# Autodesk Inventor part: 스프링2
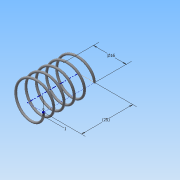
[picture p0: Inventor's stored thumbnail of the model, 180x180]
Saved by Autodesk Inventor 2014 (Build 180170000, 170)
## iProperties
Created: 2015-06
Part Number: 스프링2
Material: 강철, 연강
Document SubType Name: Modeling
Designer: Administrator
Density: 7.86 g/cm^3
Appearance: 강철
Mass: 1.52988 g
Surface Area: 7.87024 cm^2
Volume: 0.194641 cm^3
Author: Administrator
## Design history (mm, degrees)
sketch "스케치1"
  geometry: L1 (0, 0)-(8, 0); L2 (8, 0)-(8, 14.5); L3 (8, 14.5)-(0, 14.5); L4 (0, 14.5)-(0, 0); C1 r 0.5 at (8, 0)
  constraints: 8 end point, 2 parallel, 1 centre point, 1 coincident, 1 horizontal, 1 perpendicular
  dimensions: "d0" = 14.5 distance of L1.end L2.end (derived); "d1" = 16 diameter of L2 L4; "d2" = 1 diameter of C1
feature "코일1" sketch "스케치1" pitch "d3" = 10; turns "d5" = 5; dims "d4" = 14.5 (= d0), "d6" = 0, angle "d7" = 90 deg, angle "d8" = 90 deg, "d9" = 0, "d10" = 0
sketch "스케치2"
  geometry: L1 (-8.5, 0)-(-7.5, 0) reference; 1 further point
  constraints: 1 horizontal alignment
extrude "돌출1" cut sketch "스케치2" stored distance "d11" = 10; taper "d12" = 0 deg
node "작업 평면1"
sketch "스케치3"
  geometry: L1 (-7.5, 0)-(-8.5, 0) reference; 1 further point
  constraints: 1 horizontal alignment
extrude "돌출2" cut sketch "스케치3" stored distance "d14" = 10; taper "d15" = 0 deg
node "솔리드1"
node "절단 모서리 투영1"
node "절단 모서리 투영2"
other parameters: "d13" = 14.5 (= d0)
